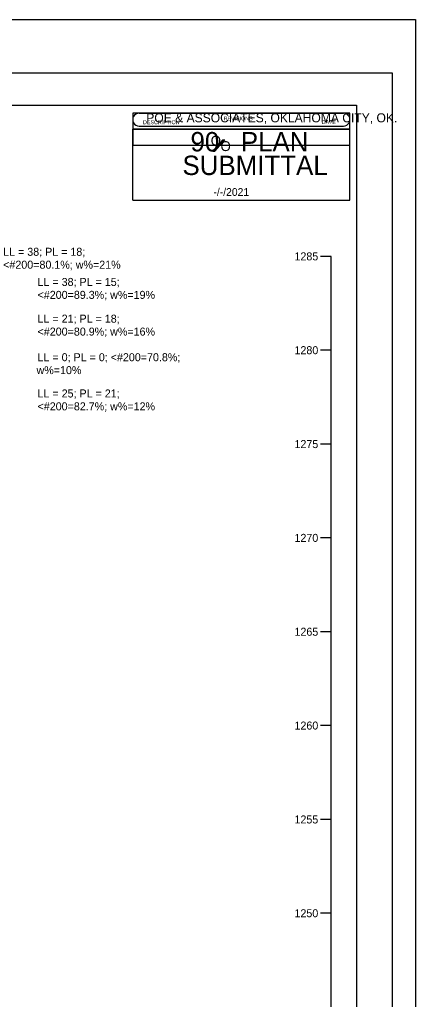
# Model space of a CAD drawing. Extents: x 7 to 126, y 24 to 56.
# Drawn here: x 78.17 to 84.3, y 38.8 to 53.97 of the extents above; entities that cross this region are included whole.
import ezdxf

# ---------------------------------------------------------------- set-up
doc = ezdxf.new("R2010")
doc.units = 0
for name, color, linetype in [('SHT_Plot_Shape_Full', 7, 'Continuous'), ('SHT_Plot_Shape_Half', 7, 'Continuous'), ('SHT_Sheet_Border', 7, 'Continuous'), ('SHT_Stamp_90_Submit', 7, 'Continuous'), ('SHT_Stamp_Rev_Block', 7, 'Continuous')]:
    doc.layers.add(name, color=color, linetype=linetype)

msp = doc.modelspace()

# ---------------------------------------------------------------- linework, layer by layer
msp.add_line((82.998, 37.223), (82.998, 50.304))
for points in [[(82.998, 50.304), (82.831, 50.304)], [(82.998, 48.851), (82.831, 48.851)], [(82.998, 47.397), (82.831, 47.397)], [(82.998, 45.944), (82.831, 45.944)], [(82.998, 44.49), (82.831, 44.49)], [(82.998, 43.037), (82.831, 43.037)], [(82.998, 41.583), (82.831, 41.583)], [(82.998, 40.13), (82.831, 40.13)]]:
    msp.add_lwpolyline(points)
at = {"layer": 'SHT_Plot_Shape_Full'}
msp.add_lwpolyline([(48.302, 53.971), (84.302, 53.971), (84.302, 29.971), (48.302, 29.971)], close=True, dxfattribs=at)
at = {"layer": 'SHT_Plot_Shape_Half'}
msp.add_lwpolyline([(49.939, 53.146), (83.939, 53.146), (83.939, 31.146), (49.939, 31.146)], close=True, dxfattribs=at)
at = {"layer": 'SHT_Sheet_Border'}
msp.add_lwpolyline([(51.889, 52.646), (83.389, 52.646), (83.389, 31.646), (51.889, 31.646)], close=True, dxfattribs=at)
at = {"layer": 'SHT_Stamp_90_Submit'}
for p, q in [((80.02, 52.522), (83.186, 52.522)), ((79.92, 52.272), (83.286, 52.272)), ((79.92, 51.173), (79.92, 52.272)), ((80.02, 52.322), (83.186, 52.322)), ((83.286, 51.173), (83.286, 52.272)), ((81.163, 51.934), (81.319, 52.107)), ((81.181, 51.934), (81.337, 52.107)), ((81.186, 51.934), (81.341, 52.107)), ((81.194, 51.934), (81.349, 52.107)), ((81.319, 52.107), (81.349, 52.107)), ((81.163, 51.934), (81.194, 51.934)), ((79.92, 51.173), (83.286, 51.173))]:
    msp.add_line(p, q, dxfattribs=at)
for centre, start, end in [((80.02, 52.422), 89.9952, 270), ((83.186, 52.422), 270, 90.0048)]:
    msp.add_arc(centre, 0.1, start, end, dxfattribs=at)
at = {"layer": 'SHT_Stamp_Rev_Block'}
for p, q in [((79.92, 52.522), (79.92, 52.022)), ((83.286, 52.522), (79.92, 52.522)), ((83.286, 52.022), (83.286, 52.522)), ((83.286, 52.272), (79.92, 52.272)), ((83.286, 52.022), (79.92, 52.022))]:
    msp.add_line(p, q, dxfattribs=at)

# ---------------------------------------------------------------- texts
for s, p in [('LL = 38; PL = 18;', (77.912, 50.313)), ('<#200=80.1%; w%=21%', (77.912, 50.113)), ('1285', (82.427, 50.242)), ('LL = 38; PL = 15;', (78.445, 49.846)), ('<#200=89.3%; w%=19%', (78.445, 49.646)), ('LL = 21; PL = 18;', (78.445, 49.277)), ('<#200=80.9%; w%=16%', (78.445, 49.077)), ('1280', (82.427, 48.789)), ('LL = 0; PL = 0; <#200=70.8%;', (78.445, 48.68)), ('w%=10%', (78.429, 48.48)), ('LL = 25; PL = 21;', (78.445, 48.119)), ('<#200=82.7%; w%=12%', (78.445, 47.919)), ('1275', (82.427, 47.335)), ('1270', (82.427, 45.882)), ('1265', (82.427, 44.428)), ('1260', (82.427, 42.975)), ('1255', (82.427, 41.521)), ('1250', (82.427, 40.068))]:
    msp.add_text(s, height=0.124).set_placement(p)
at = {"layer": 'SHT_Stamp_90_Submit'}
for s, height, p in [('POE & ASSOCIATES, OKLAHOMA CITY, OK.', 0.14, (80.13, 52.38)), ('90   PLAN', 0.3, (80.815, 51.93)), ('O', 0.153, (81.129, 52.019)), ('O', 0.153, (81.281, 51.935)), ('SUBMITTAL', 0.3, (80.691, 51.564)), ('-/-/2021', 0.12, (81.171, 51.241))]:
    msp.add_text(s, height=height, dxfattribs=at).set_placement(p)
at = {"layer": 'SHT_Stamp_Rev_Block'}
for s, height, p in [('DESCRIPTION', 0.05999, (80.08, 52.351)), ('REVISIONS', 0.06, (81.328, 52.41)), ('DATE', 0.06, (82.849, 52.355))]:
    msp.add_text(s, height=height, dxfattribs=at).set_placement(p)

doc.saveas('drawing.dxf')
